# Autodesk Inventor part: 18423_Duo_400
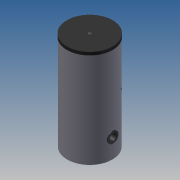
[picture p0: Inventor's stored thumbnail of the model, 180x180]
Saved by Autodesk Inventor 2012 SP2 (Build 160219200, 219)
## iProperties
allow_slope_adjustment: 0 ul
connection_type: 13 ul
flow_configuration2: 1 ul
flow_direction: 2 ul
loss_method: 0 ul
radius: 22,625 mm
radius: 15,375 mm
radius: 12,250 mm
radius: 19,625 mm
description: 0:0:18423_Duo_400
manufacturer: 0:0:Flamco Group
model: 0:0:Duo 400
url: 0:0:www.flamcogroup.com
Created: 2014-05
Part Number: 18423_Duo_400
Material: Default
Document SubType Name: Modeling
Designer: michel
Density: 1 g/cm^3
Author: michel
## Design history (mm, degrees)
sketch "Sketch1"
  geometry: C1 r 375 at (0, 0); 1 further point
  constraints: 1 centre point, 1 coincident
  dimensions: "d0" = 750 diameter of C1
extrude "Extrusion1" new body sketch "Sketch1" distance "d1" = 1630; taper "d2" = 0 deg
sketch "Sketch2"
  geometry: L1 (-375, 1630)-(375, 1630) reference; L2 (-375, 0)-(375, 0) reference; L3 (375, 0)-(375, 1630) reference; L4 (375, 1630)-(380, 1630); L5 (380, 1630)-(380, 1580); L6 (380, 1580)-(375, 1580); L7 (375, 1580)-(375, 1630); L8 (0, -326)-(0, 1956) reference; 1 further point
  constraints: 8 end point, 2 parallel, 1 horizontal, 1 perpendicular
  dimensions: "d3" = 5 distance of L5.end L6.end; "d4" = 50 distance of L4.end L5.end
revolve "Revolution1" sketch "Sketch2" stored, may be unused: angle "d5" = 90 deg
workplane "Work Plane1"
workplane "Work Plane2"
workplane "Work Plane3"
workplane "Work Plane4"
workplane "Work Plane5"
workplane "Work Plane6"
sketch "Sketch3"
  geometry: L1 (532, 1470)-(-532, 1470) reference; L2 (532, 870)-(-532, 870) reference; L3 (532, 770)-(-532, 770) reference; L4 (532, 330)-(-532, 330) reference; L5 (532, 70)-(-532, 70) reference; L6 (375, 0)-(375, 1580) reference; L7 (375, 70)-(335, 70); L8 (335, 70)-(335, 86.625); L9 (335, 86.625)-(375, 86.625); L10 (375, 86.625)-(375, 70); L11 (375, 330)-(335, 330); L12 (335, 330)-(335, 346.625); L13 (335, 346.625)-(375, 346.625); L14 (375, 346.625)-(375, 330); L15 (374.76, 770)-(334.76, 770); L16 (334.76, 770)-(334.76, 786.625); L17 (334.76, 786.625)-(374.76, 786.625); L18 (374.76, 786.625)-(374.76, 770); L19 (375, 1470)-(335, 1470); L20 (335, 1470)-(335, 1486.625); L21 (335, 1486.625)-(375, 1486.625); L22 (375, 1486.625)-(375, 1470); L23 (375, 870)-(335, 870); L24 (335, 870)-(335, 883.22); L25 (335, 883.22)-(375, 883.22); L26 (375, 883.22)-(375, 870); 1 further point
  constraints: 40 end point, 10 parallel, 5 horizontal, 5 perpendicular, 2 point on line
  dimensions: "d13" = 40 distance of L8.end L9.end; "d14" = 16.625 distance of L7.end L8.end; "d15" = 40 distance of L12.end L13.end; "d16" = 16.625 distance of L11.end L12.end; "d17" = 40 distance of L16.end L17.end; "d18" = 16.625 distance of L15.end L16.end; "d19" = 40 distance of L20.end L21.end; "d20" = 16.625 distance of L19.end L20.end; "d21" = 40 distance of L24.end L25.end; "d22" = 13.22 distance of L23.end L24.end
revolve "Revolution2" stored, may be unused: angle "d23" = 90 deg
revolve "Revolution3" stored, may be unused: angle "d24" = 90 deg
revolve "Revolution4" stored, may be unused: angle "d25" = 90 deg
revolve "Revolution5" stored, may be unused: angle "d26" = 90 deg
revolve "Revolution6" stored, may be unused: angle "d27" = 90 deg
workplane "Work Plane7"
sketch "Sketch4"
  geometry: C1 r 15.375 at (0, 1470); C2 r 12.25 at (0, 870); C3 r 15.375 at (0, 770); C4 r 15.375 at (0, 330); C5 r 15.375 at (0, 70); 1 further point
  constraints: 5 centre point
  dimensions: "d28" = 30.75 diameter of C1; "d29" = 24.5 diameter of C2; "d30" = 30.75 diameter of C3; "d31" = 30.75 diameter of C4; "d32" = 30.75 diameter of C5
extrude "Extrusion2" cut sketch "Sketch4" distance "d33" = 40; taper "d34" = 0 deg
sketch "Sketch5"
  geometry: L1 (-375, 0)-(-375, 1580) reference; L2 (-375, 0)-(-375, 327); L3 (-249, 327)-(-623, 327); L4 (-375, 327)-(-387.5, 327); L5 (-387.5, 327)-(-387.5, 417); L6 (-387.5, 417)-(-375, 417); L7 (-375, 417)-(-375, 327); 1 further point
  constraints: 12 end point, 2 parallel, 2 perpendicular, 1 horizontal, 1 point on line
  dimensions: "d35" = 327 distance of L1.start L2.end; "d36" = 12.5 distance of L5.end L6.end; "d37" = 90 distance of L4.end L5.end
revolve "Revolution7" sketch "Sketch5" stored, may be unused: angle "d38" = 90 deg
sketch "Sketch6"
  geometry: C1 r 62.5 at (0, 0); A1 r 90 centre (0, 0) between (90, 0) and (-90, 0) reference; 1 further point
  constraints: 1 centre point, 1 coincident
  dimensions: "d39" = 125 diameter of C1
extrude "Extrusion3" join sketch "Sketch6" stored distance "d40" = 40; taper "d41" = 0 deg
sketch "Sketch7"
  geometry: C1 r 90 at (0, 0) reference; C2 r 55 at (0, 0); 1 further point
  constraints: 1 centre point, 1 coincident
  dimensions: "d42" = 110 diameter of C2
extrude "Extrusion4" cut sketch "Sketch7" distance "d43" = 80; taper "d44" = 0 deg
sketch "Sketch8"
  geometry: C1 r 380 at (0, 0) reference; C2 r 20.955 at (0, 0)
  constraints: 1 centre point, 1 coincident
  dimensions: "d45" = 41.91 diameter of C2
extrude "Extrusion5" join sketch "Sketch8" distance "d46" = 2; taper "d47" = 0 deg
sketch "Sketch9"
  geometry: C1 r 20.955 at (0, 0) reference; C2 r 19.625 at (0, 0)
  constraints: 1 centre point, 1 coincident
  dimensions: "d48" = 39.25 diameter of C2
extrude "Extrusion6" cut sketch "Sketch9" distance "d49" = 40; taper "d50" = 0 deg
workplane "Work Plane8"
sketch "Sketch10"
  geometry: L1 (0, 375)-(1580, 375) reference; L2 (870, -742.16)-(870, 748.304) reference; L3 (870, 375)-(893.9, 375); L4 (893.9, 375)-(893.9, 335); L5 (893.9, 335)-(870, 335); L6 (870, 335)-(870, 375); 1 further point
  constraints: 8 end point, 2 parallel, 2 point on line, 1 horizontal, 1 perpendicular
  dimensions: "d52" = 23.9 distance of L4.end L5.end; "d53" = 40 distance of L3.end L4.end
revolve "Revolution8" sketch "Sketch10" stored, may be unused: angle "d54" = 90 deg
sketch "Sketch11"
  geometry: C1 r 22.625 at (0, 0); A1 r 23.9 centre (0, 0) between (23.9, 0) and (-23.9, 0) reference; 1 further point
  constraints: 1 centre point, 1 coincident
  dimensions: "d55" = 45.25 diameter of C1
extrude "Extrusion7" cut sketch "Sketch11" distance "d56" = 40; taper "d57" = 0 deg
sketch "Sketch12"
  geometry: C1 r 22.625 at (0, 0) reference; A1 r 23.9 centre (0, 0) between (-23.9, 0) and (23.9, 0) reference; A2 r 23.9 centre (0, 0) between (23.9, 0) and (-23.9, 0) reference; 1 further point
extrude "Extrusion8" join sketch "Sketch12" distance "d58" = 1; taper "d59" = 0 deg
sketch "Sketch13"
  geometry: C1 r 15.375 at (0, 0) reference; C2 r 15.375 at (260, 0) reference; C3 r 12.25 at (800, 0) reference; C4 r 15.375 at (1400, 0) reference; A1 r 16.625 centre (0, 0) between (16.625, 0) and (-16.625, 0) reference; A2 r 16.625 centre (0, 0) between (-16.625, 0) and (16.625, 0) reference; A3 r 16.625 centre (260, 0) between (276.625, 0) and (243.375, 0) reference; A4 r 16.625 centre (260, 0) between (243.375, 0) and (276.625, 0) reference; A5 r 13.22 centre (800, 0) between (813.22, 0) and (786.78, 0) reference; A6 r 13.22 centre (800, 0) between (786.78, 0) and (813.22, 0) reference; A7 r 16.625 centre (1400, 0) between (1416.625, 0) and (1383.375, 0) reference; A8 r 16.625 centre (1400, 0) between (1383.375, 0) and (1416.625, 0) reference; 1 further point
extrude "Extrusion9" join sketch "Sketch13" distance "d60" = 1; taper "d61" = 0 deg
body "Solid1"
node "Projected Loop1"
node "Projected Loop2"
node "Projected Loop3"
node "Projected Loop4"
other parameters: "d12" = 0, "d51" = 35 deg
